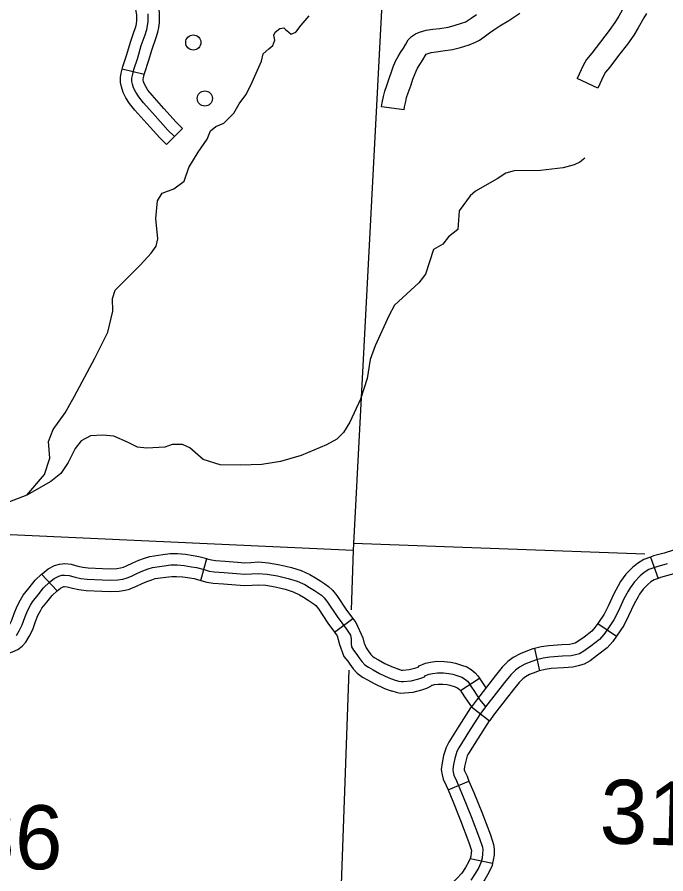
# Model space of a CAD drawing. Extents: x 653372 to 905732, y 627442 to 787275.
# Drawn here: x 718732 to 723010, y 744138 to 749788 of the extents above; entities that cross this region are included whole.
import ezdxf

# ---------------------------------------------------------------- set-up
doc = ezdxf.new("R2010")
doc.units = 0
for name, color, linetype in [('32', 7, 'Continuous'), ('35', 7, 'Continuous'), ('4', 7, 'Continuous'), ('45', 7, 'Continuous'), ('46', 7, 'Continuous'), ('5', 7, 'Continuous'), ('56', 7, 'Continuous')]:
    doc.layers.add(name, color=color, linetype=linetype)

msp = doc.modelspace()

# ---------------------------------------------------------------- linework, layer by layer
at = {"layer": '32'}
for p, q in [((719570.5, 749408.9), (719424.7, 749444.3)), ((719822.2, 749054.2), (719717.1, 748947.2)), ((722907.8, 746227.6), (722959.6, 746086.9)), ((722560.5, 745789.8), (722684.9, 745705.9)), ((722142.7, 745624.2), (722176.3, 745478)), ((721727.3, 745239.8), (721846.2, 745148.4)), ((721573.4, 744692.2), (721711.6, 744750.5)), ((721720.2, 744239.6), (721866.9, 744208))]:
    msp.add_line(p, q, dxfattribs=at)
for points in [[(719570.5, 749408.9), (719573.7, 749422), (719599.3, 749498.3), (719621.9, 749577.5), (719646.8, 749646.4), (719660.3, 749688.4), (719666, 749719), (719671, 749751.7), (719671.7, 749776.6), (719670.3, 749817.7), (719663.2, 749860.5), (719651.9, 749947.9)], [(719424.7, 749444.3), (719429.4, 749463.7), (719456, 749542.8), (719479.1, 749623.7), (719504.8, 749694.8), (719514.6, 749725.2), (719518.1, 749744.1), (719521.3, 749765.3), (719521.7, 749776.2), (719520.7, 749802.6), (719514.7, 749838.7), (719503.2, 749928.8)], [(719769.6, 749000.7), (719726.7, 749042.9), (719643.3, 749136.7), (719565.7, 749224.1), (719533.7, 749262.7), (719514.8, 749293.7), (719500.1, 749321.2), (719492.6, 749345.2), (719489.3, 749364.6), (719488.8, 749386.2), (719492.1, 749403.9), (719501.6, 749442.8), (719527.7, 749520.6), (719550.5, 749600.6), (719575.8, 749670.6), (719587.4, 749706.8), (719592, 749731.5), (719596.2, 749758.5), (719596.7, 749776.4), (719595.5, 749810.1)], [(719717.1, 748947.2), (719672.3, 748991.2), (719587.2, 749086.9), (719508.8, 749175.3), (719472.6, 749218.9), (719449.6, 749256.4), (719430.7, 749292.1), (719419.5, 749327.6), (719414.4, 749357.6), (719413.7, 749392.4), (719418.7, 749419.6), (719424.7, 749444.3)], [(719822.2, 749054.2), (719781, 749094.7), (719699.3, 749186.5), (719622.7, 749273), (719594.9, 749306.5), (719579.9, 749330.9), (719569.6, 749350.3), (719565.6, 749362.8), (719564.1, 749371.7), (719564, 749380.1), (719565.5, 749388.1), (719570.5, 749408.9)], [(723314.5, 746444.8), (723286.6, 746399.2), (723268.9, 746377.5), (723233.8, 746341.8), (723230.8, 746339.8), (723199.9, 746324.7), (723175.7, 746314.3), (723061.1, 746272.7), (722998, 746254), (722928.3, 746235.2), (722907.8, 746227.6)], [(723442.5, 746366.6), (723409.3, 746312.3), (723380.7, 746277.3), (723330.6, 746226.3), (723306.6, 746209.8), (723262.5, 746188.4), (723231.2, 746174.8), (723108.1, 746130.2), (723038.9, 746109.6), (722973.8, 746092.1), (722959.6, 746086.9)], [(722907.8, 746227.6), (722865.3, 746212), (722823.6, 746186), (722789.6, 746158), (722746.6, 746113.7), (722710.6, 746066.5), (722694.8, 746038.7), (722666.1, 745985.4), (722628.7, 745904.3), (722602.7, 745851.9), (722564.5, 745795.8), (722560.5, 745789.8)], [(723018.5, 746181.8), (722951, 746163.7), (722898.4, 746144.3), (722867.5, 746124.9), (722840.4, 746102.8), (722803.5, 746064.7), (722773.3, 746025), (722760.4, 746002.4), (722733.2, 745951.9), (722696.4, 745871.9), (722667.6, 745814), (722626.6, 745753.7), (722601.2, 745716), (722571.8, 745683.7), (722515.1, 745640.1), (722469.5, 745607), (722440.6, 745590.3), (722413.4, 745582.4), (722385.5, 745576.5), (722328.6, 745572.8), (722245.4, 745566.5), (722199.9, 745560.4), (722155.7, 745550.2), (722124.9, 745538.3), (722079.8, 745520.1), (722044.1, 745501.5), (722017.8, 745481.4), (721986.5, 745450.6), (721945.8, 745400.4), (721821.2, 745238.9), (721783.4, 745189.7), (721709, 745073), (721643.7, 744969.5), (721630.8, 744944.2), (721617.3, 744900), (721608.6, 744858.4), (721604.3, 744826.1), (721607.1, 744807.8), (721612.6, 744790), (721629.7, 744751.7), (721673.9, 744646.9), (721726.1, 744517.4), (721781.8, 744370.5), (721799.7, 744315.2), (721802.5, 744296.2), (721801.7, 744269.8), (721797.5, 744242.3), (721792, 744216.7), (721776.1, 744180.7), (721752.4, 744139.9), (721722.7, 744096.2)], [(722959.6, 746086.9), (722931.6, 746076.6), (722911.3, 746063.9), (722891.3, 746047.5), (722860.4, 746015.7), (722836, 745983.6), (722826.1, 745966.1), (722800.4, 745918.4), (722764, 745839.5), (722732.5, 745776), (722688.7, 745711.7), (722684.9, 745705.9)], [(722560.5, 745789.8), (722542, 745762.4), (722520.8, 745739.1), (722470.2, 745700.2), (722428.6, 745670), (722410.9, 745659.8), (722395, 745655.2), (722375.2, 745650.9), (722323.4, 745647.6), (722237.6, 745641.1), (722186.5, 745634.3), (722142.7, 745624.2)], [(722684.9, 745705.9), (722660.3, 745669.5), (722622.8, 745628.3), (722560, 745580.1), (722510.4, 745544.1), (722470.4, 745520.9), (722431.7, 745509.6), (722395.8, 745502), (722333.9, 745497.9), (722253.1, 745491.8), (722213.3, 745486.5), (722176.3, 745478)], [(722142.7, 745624.2), (722133.6, 745622.1), (722097.3, 745608.1), (722048.4, 745588.3), (722003.7, 745565.1), (721968.5, 745538.1), (721930.9, 745501.1), (721887, 745447), (721761.8, 745284.6), (721727.3, 745239.8)], [(722177.7, 745478.3), (722152.5, 745468.6), (722111.2, 745451.9), (722084.5, 745438), (722067.1, 745424.7), (722042.1, 745400), (722004.6, 745353.9), (721880.6, 745193.1), (721846.2, 745148.4)], [(721727.3, 745239.8), (721721.9, 745232.8), (721645.6, 745113.2), (721578.5, 745006.7), (721561, 744972.5), (721544.6, 744918.7), (721534.6, 744871.1), (721528.5, 744825.4), (721533.8, 744790.8), (721542.4, 744763.5), (721560.9, 744721.8), (721573.4, 744692.2)], [(721846.2, 745148.4), (721844.9, 745146.6), (721772.3, 745032.8), (721709, 744932.4), (721700.6, 744916), (721690, 744881.4), (721682.6, 744845.7), (721680, 744826.8), (721680.4, 744824.8), (721682.9, 744816.6), (721698.5, 744781.5), (721711.6, 744750.5)], [(721711.6, 744750.5), (721743.2, 744675.5), (721795.9, 744544.8), (721852.6, 744395.3), (721873, 744332.4), (721877.7, 744300.6), (721876.6, 744263), (721871.3, 744228.7), (721866.9, 744208)], [(721573.4, 744692.2), (721604.5, 744618.4), (721656.2, 744490.1), (721711, 744345.6), (721726.4, 744298), (721727.4, 744291.8), (721726.9, 744276.7), (721723.7, 744255.8), (721720.2, 744239.6)], [(721720.3, 744240.1), (721709.2, 744214.8), (721688.9, 744179.8), (721663.9, 744143), (721631.3, 744107.9), (721597.7, 744076.9), (721553.8, 744035.5), (721523.4, 744000.8), (721503.5, 743965.9), (721489.3, 743920.7), (721468.6, 743858.5), (721418.2, 743700.6)], [(721866.9, 744208), (721863.7, 744193.4), (721843, 744146.7), (721816, 744100), (721781.6, 744049.4), (721737.4, 744001.6), (721700.1, 743967.2), (721661.9, 743931.3), (721646.2, 743913.3), (721641.8, 743905.7), (721632.1, 743874.6), (721611.2, 743811.9), (721578.5, 743709.4)]]:
    msp.add_lwpolyline(points, dxfattribs=at)
at = {"layer": '35'}
for points in [[(720161.1, 749154.1), (720196.8, 749216.6), (720240.3, 749274.9), (720272, 749339.6), (720344.4, 749498.6), (720353.8, 749546.1), (720392.6, 749578.7), (720419.1, 749601.8), (720431.5, 749636.2), (720425.1, 749669.2), (720433.7, 749688.9), (720463.6, 749712.8), (720490.5, 749716.9), (720501.3, 749706), (720523.7, 749688.6), (720539.1, 749676.7), (720569.3, 749688.8), (720604.1, 749735.5), (720657.1, 749796.5)], [(718796.9, 746636.4), (718912.3, 746772.6), (718947.3, 746879), (718938.7, 746990.6), (718968.9, 747069.3), (719047.8, 747178.3), (719110.7, 747287.9), (719245.5, 747538.4), (719330.2, 747710.9), (719362.2, 747849.2), (719360.8, 747932.8), (719378.3, 747988), (719468.5, 748076.8), (719546.4, 748154), (719616.3, 748231.5), (719649.6, 748278.2), (719658.9, 748325.7), (719647.1, 748461.3), (719658.5, 748576.4), (719687.9, 748627.2), (719764.3, 748656.7), (719833.4, 748706.4), (719864, 748797), (719926.7, 748898.5), (719985, 748984.3), (720006.5, 749039.4), (720043.1, 749066.1), (720095.5, 749088.4), (720161.1, 749154.1)], [(722474.6, 748857.3), (722442.9, 748831.2), (722404.5, 748813.2), (722332, 748795.2), (722182.6, 748776.4), (722009.6, 748774.2), (721954.2, 748758.7), (721898.4, 748721.3), (721754.3, 748641.2), (721719.4, 748610.1), (721646.7, 748511.1), (721638.2, 748387), (721577.1, 748339.5), (721540.1, 748290.4), (721477.9, 748255.4), (721425.1, 748093.8), (721381.5, 748034.9), (721220.5, 747889.3), (721183.5, 747819.2), (721093, 747620.6), (721060.5, 747529.4), (721039.9, 747404.8), (720996.1, 747268.9), (720925.9, 747117.7), (720885, 747048.7), (720840.8, 747004.9), (720772.8, 746967.8), (720605, 746896.4), (720468, 746857.2), (720345.6, 746837.6), (720205.6, 746832.5), (720070.8, 746835.2), (719957.9, 746870.4), (719871.3, 746947.5), (719822.6, 746969.3), (719753.7, 746970.2), (719705, 746952.4), (719587.3, 746946.2), (719525.5, 746952.9), (719459.5, 746984.3), (719369.4, 747024.6), (719296.1, 747031.6), (719216, 747027.5)], [(719216, 747027.5), (719153.6, 746993.7), (719114.3, 746943.2), (719067.8, 746851.1), (719019.9, 746778.9), (718954.6, 746725.2), (718796.9, 746636.4), (718654, 746581), (718581.8, 746559.3), (718497.2, 746524.1), (718416.2, 746474.8), (718325, 746419.8), (718286.6, 746399.1), (718260.9, 746386.9)]]:
    msp.add_lwpolyline(points, dxfattribs=at)
at = {"layer": '4'}
for points in [[(721233.1, 751764.2), (721228.8, 751646.3), (721221.8, 751511.4), (720950, 746316.4), (720948.4, 746271.3), (720934.1, 745879.3)], [(720919.6, 745481.8), (720856.9, 743763.2)]]:
    msp.add_lwpolyline(points, dxfattribs=at)
at = {"layer": '45'}
for p, q in [((719944.1, 746072.6), (719984, 746217.1)), ((718995.9, 746005.1), (718893.1, 746114.3)), ((720825.1, 745731.8), (720945.3, 745821.6)), ((721654.7, 745346.8), (721780.3, 745428.8))]:
    msp.add_line(p, q, dxfattribs=at)
for points in [[(719432.4, 746160.7), (719454.2, 746170.4), (719494.2, 746190.4), (719534.5, 746207.3), (719571.8, 746220.1), (719608, 746232), (719692.4, 746243.5), (719741.2, 746250.2), (719789.4, 746250.3), (719841.9, 746245.9), (719893.3, 746237.9), (719930.6, 746231.9), (719984, 746217.1)], [(719984.1, 746217.1), (719985.6, 746216.7), (720013.7, 746208.1), (720039.5, 746205), (720102.8, 746199.5), (720184.4, 746194.6), (720233.8, 746190.3), (720273.5, 746192.4), (720323.1, 746195), (720390.3, 746190.1), (720464.9, 746177.2), (720504.8, 746167.6)], [(718893, 746114.3), (718896.5, 746117.6), (718935.7, 746149.4), (718979.3, 746171.5), (719012.1, 746181.4), (719045.9, 746184), (719087.6, 746179.8), (719133.2, 746167.9), (719165.4, 746160.8), (719200.9, 746155.4), (719294.5, 746152), (719348.4, 746150.3), (719389.7, 746152.4), (719414.1, 746155.8), (719434.5, 746161.3)], [(719193.8, 746080.6), (719292.1, 746077), (719349.2, 746075.3), (719396.7, 746077.6), (719429.2, 746082.2), (719457.5, 746089.9), (719486.2, 746102.5), (719525.5, 746122.2), (719561.2, 746137.1), (719595.7, 746149), (719624.9, 746158.6), (719702.6, 746169.2), (719746.4, 746175.2), (719786.4, 746175.3), (719833, 746171.4), (719881.6, 746163.8), (719914.6, 746158.5), (719964.6, 746144.7), (719998.1, 746134.5), (720031.8, 746130.4), (720097.3, 746124.7), (720178.9, 746119.8), (720232.5, 746115.1), (720277.4, 746117.5), (720322.4, 746119.8), (720381.2, 746115.6), (720449.7, 746103.7), (720519.9, 746086.8), (720578.3, 746067.9), (720628.6, 746046.1), (720660.6, 746027.3), (720692.6, 746006.7), (720719.1, 745988.7), (720738.4, 745975.8), (720756.3, 745958), (720778.8, 745930.3), (720841.7, 745835), (720903.7, 745752), (720930.1, 745711.8), (720935.6, 745687.7), (720934, 745654.6), (720936.7, 745634.3), (720949, 745614.3), (720972.4, 745584.6), (720986, 745565.2), (721006, 745538.1), (721023.9, 745517.3), (721047.9, 745500.6), (721078.8, 745484.3), (721121.7, 745459.7), (721182.3, 745430.8), (721224.8, 745416), (721249.2, 745409.1), (721263.3, 745406.2), (721280.5, 745406.9), (721329.4, 745411.6), (721380.2, 745424.8), (721406.9, 745432.7), (721417.5, 745437.9), (721425.7, 745445.6), (721448.1, 745455.4), (721471, 745460.2), (721504.9, 745464.7), (721543.6, 745464.2), (721579.6, 745460), (721604.6, 745455), (721638.7, 745444.1), (721664.2, 745434.8), (721681.7, 745424.4), (721700.9, 745408.5), (721711, 745397.7), (721724.6, 745377), (721748.7, 745340.6), (721781.5, 745288), (721804.6, 745259.7), (721821.2, 745238.9)], [(720504.8, 746167.6), (720540.2, 746159.1), (720604.8, 746138.1), (720662.6, 746113.1), (720700, 746091.2), (720734, 746069.2), (720761, 746050.9), (720786, 746034.1), (720811.9, 746008.5), (720839.3, 745974.7), (720903.1, 745878.1), (720945.3, 745821.6)], [(718606.1, 745728.3), (718647.2, 745742.9), (718660.7, 745748.7), (718664.1, 745751.3), (718667.4, 745754.8), (718679.1, 745775.7), (718697.2, 745810.3), (718713.1, 745854.9), (718732.6, 745903.2), (718754.3, 745945.8), (718772.6, 745975.6), (718810.9, 746023.9), (718851.2, 746074.8), (718893.1, 746114.3)], [(718728.5, 745710.4), (718745.1, 745740), (718766.1, 745780.2), (718783.2, 745828.2), (718801, 745872.1), (718819.8, 745909.1), (718834.2, 745932.6), (718869.7, 745977.3), (718906.6, 746024), (718946, 746061.1), (718976.8, 746086.1), (719007.3, 746101.6), (719025.9, 746107.2), (719045, 746108.7), (719074.3, 746105.7), (719115.7, 746094.9), (719151.6, 746087), (719193.8, 746080.6)], [(719473.8, 746016.6), (719482.6, 746019), (719518.1, 746034.7), (719556.8, 746054), (719587.8, 746067), (719619.6, 746077.9), (719641.8, 746085.2), (719712.8, 746094.9), (719751.6, 746100.2), (719783.3, 746100.3), (719824.1, 746096.9), (719869.9, 746089.7), (719898.7, 746085.1), (719944.1, 746072.6)], [(719943.6, 746072.7), (719982.5, 746060.8), (720024, 746055.8), (720091.9, 746049.9), (720173.4, 746045), (720231.2, 746040), (720281.3, 746042.6), (720321.6, 746044.7), (720372.1, 746041.1), (720434.5, 746030.2), (720469.8, 746021.7)], [(718656.3, 745586.9), (718702.3, 745603.3), (718735.9, 745617.9), (718764.6, 745639), (718789.6, 745666), (718811, 745704.3), (718835, 745750.1), (718853.4, 745801.6), (718869.3, 745841), (718885.3, 745872.5), (718895.8, 745889.6), (718928.5, 745930.7), (718962, 745973.2), (718995.9, 746005.1)], [(718995.4, 746004.6), (719017.8, 746022.9), (719035.2, 746031.7), (719039.7, 746033), (719044.2, 746033.4), (719061, 746031.7), (719098.1, 746022), (719137.9, 746013.3), (719186.8, 746005.8), (719289.6, 746002), (719349.9, 746000.2), (719403.8, 746002.9), (719444.3, 746008.6), (719473.8, 746016.6)], [(720469.8, 746021.7), (720499.5, 746014.6), (720551.7, 745997.6), (720594.6, 745979.1), (720621.3, 745963.4), (720651.2, 745944.1), (720677.2, 745926.5), (720690.7, 745917.4), (720700.6, 745907.6), (720718.2, 745885.9), (720780.3, 745791.8), (720825.1, 745731.8)], [(720945.3, 745821.6), (720965.1, 745795.1), (721011, 745694.2), (721021.1, 745657.7), (721022.5, 745655.5), (721032.7, 745629.3), (721046.9, 745609), (721064.7, 745584.9), (721074.6, 745573.4), (721087, 745564.8), (721115, 745550), (721156.5, 745526.1), (721210.8, 745500.3), (721248.3, 745487.2)], [(720825.1, 745731.8), (720842.3, 745708.9), (720858.7, 745651.3), (720887.4, 745571.3), (720912.1, 745539.9), (720925.1, 745521.4), (720947.4, 745491.3), (720973.2, 745461.2), (721008.9, 745436.4), (721042.6, 745418.6), (721086.8, 745393.2), (721153.7, 745361.3), (721199.1, 745345.5)], [(721247.4, 745487.6), (721267, 745482), (721269.3, 745481.5), (721275.4, 745481.8), (721316.3, 745485.7), (721360.2, 745497.1), (721375.9, 745501.7), (721383.8, 745509.1), (721425.1, 745527.2), (721458.3, 745534.2), (721500.5, 745539.8), (721548.5, 745539.1), (721591.3, 745534.2), (721623.5, 745527.7), (721663, 745515.1), (721696.5, 745502.8), (721725.1, 745485.9), (721752.4, 745463.2), (721770.2, 745444.3), (721780.3, 745428.8)], [(721780.3, 745428.8), (721787.2, 745418.2), (721823.1, 745364.1)], [(721199.1, 745345.5), (721202.3, 745344.4), (721231.5, 745336.2), (721257.2, 745330.9), (721285.6, 745332.1), (721342.5, 745337.5), (721400.2, 745352.6), (721434.1, 745362.5), (721460.7, 745375.5), (721467.6, 745382.1), (721471.1, 745383.6), (721483.7, 745386.3), (721509.4, 745389.7), (721538.8, 745389.3), (721567.8, 745385.9), (721585.7, 745382.3), (721614.4, 745373.2), (721631.9, 745366.7), (721638.4, 745362.9), (721649.5, 745353.7), (721651.9, 745351.1), (721654.7, 745346.8)], [(721654.7, 745346.8), (721661.9, 745335.8), (721685.6, 745300.1), (721727.3, 745239.8)]]:
    msp.add_lwpolyline(points, dxfattribs=at)
at = {"layer": '46'}
for points in [[(722783.7, 750032.7), (722775.4, 749982.3), (722770.1, 749941.3), (722765.6, 749920.7), (722762, 749907.2), (722759.2, 749900.6), (722751.6, 749886.6), (722734, 749858.2), (722698.6, 749793.5), (722673.7, 749753.5), (722636, 749700.4), (722577.7, 749625.3), (722522.2, 749551.5), (722486.7, 749509.9), (722464.5, 749468.8), (722425.1, 749382.6)], [(721283.9, 749175.9), (721135.3, 749196.6), (721138.9, 749222.2), (721147.8, 749265.2), (721156.3, 749300.5), (721169.1, 749338.1), (721188.2, 749390.6), (721199.7, 749427.5), (721211.3, 749460), (721227.3, 749498.4), (721243.8, 749528), (721260.7, 749554.6), (721279, 749584.4), (721294.5, 749610.1), (721310.7, 749637.9), (721332, 749660), (721359.4, 749677.6), (721385, 749688.1), (721428.9, 749701.3), (721474, 749708.5), (721519.4, 749714.2), (721573.5, 749722.3), (721614.8, 749732), (721662.8, 749747.6), (721689.9, 749758), (721698.9, 749763.3), (721725.8, 749782.1), (721760.7, 749806.5)], [(721283.9, 749175.9), (721286.8, 749196.6), (721294.2, 749232.4), (721300.5, 749258.6), (721310.6, 749288.3), (721330.4, 749342.6), (721342, 749379.9), (721351.3, 749405.9), (721362.5, 749432.9), (721372.8, 749451.3), (721387.9, 749475.1), (721407.1, 749506.3), (721423.6, 749533.6), (721429.8, 749544.4), (721435.1, 749546.5), (721462.5, 749554.7), (721495.2, 749560), (721539.8, 749565.5), (721602, 749574.8), (721655.3, 749587.5), (721712.8, 749606.2), (721755.3, 749622.4), (721780, 749637), (721811.8, 749659.1), (721847.1, 749683.9), (721875.4, 749704), (721913.9, 749729.9), (721974.1, 749766.1), (722047.2, 749813.4)], [(722881.6, 749811.5), (722863.7, 749782.6), (722828.2, 749717.8), (722798.6, 749670.3), (722756.4, 749611), (722696.9, 749534.2), (722639.3, 749457.7), (722611.1, 749424.6), (722598.8, 749401.9), (722561.6, 749320.3), (722425.1, 749382.6)]]:
    msp.add_lwpolyline(points, dxfattribs=at)
at = {"layer": '5'}
for points in [[(720948.4, 746271.3), (718300.1, 746391.4)], [(722870.3, 746245.7), (720950, 746316.4)]]:
    msp.add_lwpolyline(points, dxfattribs=at)
at = {"layer": '56'}
for centre in [(719893.8, 749621.3), (719970, 749251.8)]:
    msp.add_circle(centre, 50, dxfattribs=at)

# ---------------------------------------------------------------- texts
at = {"layer": '5'}
for s, p in [('31', (722569.9, 744340.9)), ('36', (718398.4, 744183))]:
    msp.add_text(s, height=422.4, rotation=358.28, dxfattribs=at).set_placement(p)

doc.saveas('drawing.dxf')
